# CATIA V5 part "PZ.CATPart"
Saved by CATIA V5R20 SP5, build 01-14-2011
Part number: PZ
Bounding box of the stored display mesh (mm): x -25 to 25, y -25 to 25, z 0 to 110
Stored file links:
  E:\PZ.CATPart
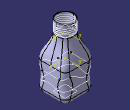
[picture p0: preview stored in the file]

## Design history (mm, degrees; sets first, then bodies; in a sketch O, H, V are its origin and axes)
Set1
  Sketch1 on xy-plane, origin (0, 0, 0), H (1, 0, 0), V (0, 1, 0)
    line L1 (25, 25) -> (25, -25)
    line L2 (25, -25) -> (-25, -25)
    line L3 (-25, -25) -> (-25, 25)
    line L4 (-25, 25) -> (25, 25)
    length L4 = 50
    length L1 = 50
    vertical: L1 V, L3 V
    horizontal: L2 H, L4 H
    equidistance: L1 L3 O, L2 L4 O
Body1 (main body)
  Pad1: profile Sketch1, direction (0, 0, 1), length 50
  Fillet1: on edge [face of Pad1 from Sketch1.L4 | face of Pad1 from Sketch1.L1]; edge [face of Pad1 from Sketch1.L3 | face of Pad1 from Sketch1.L4]; edge [face of Pad1 from Sketch1.L2 | face of Pad1 from Sketch1.L3]; edge [face of Pad1 from Sketch1.L1 | face of Pad1 from Sketch1.L2]
  Fillet2: radius 8, on start face of Pad1
  Plane1: type Offset, RefPlane xy-plane, Offset 90
  Sketch2 on Plane1, origin (0, 0, 90), H (1, 0, 0), V (0, 1, 0)
    circle A1 centre (0, 0) radius 15
  Sketch3 on Plane1, origin (0, 0, 90), H (1, 0, 0), V (0, 1, 0)
  Pad2: profile Sketch2, direction (0, 0, 1), length 20
  Sketch4 on Plane1, origin (0, 0, 90), H (1, 0, 0), V (0, 1, 0)
    point P1 (15, 0)
  Sketch5 on end face of Pad1, origin (0, 0, 50), H (1, 0, 0), V (0, 1, 0)
    point P1 (25, 0)
    coincidence: P1 H
  Loft1: solid, Sections ({boundary Boundary {extract ExtractElem end face of Pad1}}; {boundary Boundary {extract ExtractElem start face of Pad2}}), StartFace end face of Pad1, EndFace start face of Pad2
  Sketch6 on face of Pad1 from Sketch1.L1, origin (25, 0, 0), H (0, 1, 0), V (0, 0, 1)
    spline S1 through (-40.9131, 20.2151) (-36.9075, 14.36) (-7.0867, 22.9943) (9.0869, 20.2151) (30.1188, 23.7219)
  Extrude1: Lim1 60, Lim2 0, Element1 Sketch6
  MultiSel1: CommonCtxFeats ({extract ExtractElem face of Pad1 from Sketch1.L2}; {extract ExtractElem face of Fillet1}; {extract ExtractElem face of Fillet1}; {extract ExtractElem face of Pad1 from Sketch1.L1}; {extract ExtractElem face of Fillet1}; {extract ExtractElem face of Pad1 from Sketch1.L4}; {extract ExtractElem face of Fillet1}; {extract ExtractElem face of Pad1 from Sketch1.L3})
  Join1: Elements ({intersect ToIntersect1 {extract ExtractElem face of Pad1 from Sketch1.L2}, ToIntersect2 Extrude1}; {intersect ToIntersect1 {extract ExtractElem face of Fillet1}, ToIntersect2 Extrude1}; {intersect ToIntersect1 {extract ExtractElem face of Fillet1}, ToIntersect2 Extrude1}; {intersect ToIntersect1 {extract ExtractElem face of Pad1 from Sketch1.L1}, ToIntersect2 Extrude1}; {intersect ToIntersect1 {extract ExtractElem face of Fillet1}, ToIntersect2 Extrude1}; {intersect ToIntersect1 {extract ExtractElem face of Fillet1}, ToIntersect2 Extrude1}; {intersect ToIntersect1 {extract ExtractElem face of Pad1 from Sketch1.L3}, ToIntersect2 Extrude1}; {intersect ToIntersect1 {extract ExtractElem face of Pad1 from Sketch1.L4}, ToIntersect2 Extrude1})
  Shell1: ExtOffset 0, Face end face of Pad2, IntOffset 1
  Sketch7 on face of Pad1 from Sketch1.L2, origin (0, -25, 0), H (1, 0, 0), V (0, 0, 1)
    spline S1 through (-40, 30) (-30, 40) (-10, 30) (10, 40) (30, 30)
  Extrude2: Lim1 60, Lim2 0, Element1 Sketch7
  MultiSel2: CommonCtxFeats ({extract ExtractElem face of Pad1 from Sketch1.L1}; {extract ExtractElem face of Fillet1}; {extract ExtractElem face of Pad1 from Sketch1.L2}; {extract ExtractElem face of Fillet1}; {extract ExtractElem face of Pad1 from Sketch1.L4}; {extract ExtractElem face of Fillet1}; {extract ExtractElem face of Pad1 from Sketch1.L3}; {extract ExtractElem face of Fillet1})
  Point1: type OnSurface, Support face of Pad2 from Sketch2.A1, Length 25.5962, Direction (-0.9205, 0, -0.3907)
  Helix1: Direction Z axis, RefPoint Point1, Pitch 3, Height 16, TaperAngle 0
